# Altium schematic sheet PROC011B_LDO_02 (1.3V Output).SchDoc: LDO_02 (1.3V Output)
size 431 x 279 mm; Date: Not shown in title block; ApprovedBy: Not shown in title block; CheckedBy: Not shown in title block; Author: Not shown in title block; CompanyName: Not shown in title block; Engineer: Not shown in title block; Organization: Not shown in title block; Address1: Not shown in title block; Address2: Not shown in title block; Address3: Not shown in title block; Address4: Not shown in title block; DocumentNumber: 1; Revision: Use project parameter SCH_Rev; SheetNumber: 5; SheetTotal: 17; PageSetup: Record=PageOptions¦CenterHorizontal=True¦CenterVertical=True¦PrintScale=1.00¦XCorrection=1.00¦YCorrection=1.00¦PrintKind=0¦BorderSize=5000000¦LeftOffset=0¦BottomOffset=0¦Orientation=2¦PaperLength=1000¦PaperWidth=1000¦Scale=100¦PaperSource=15¦PrintQuality=600¦MediaType=1¦DitherType=10¦PaperKind=Letter¦PrintScaleMode=1
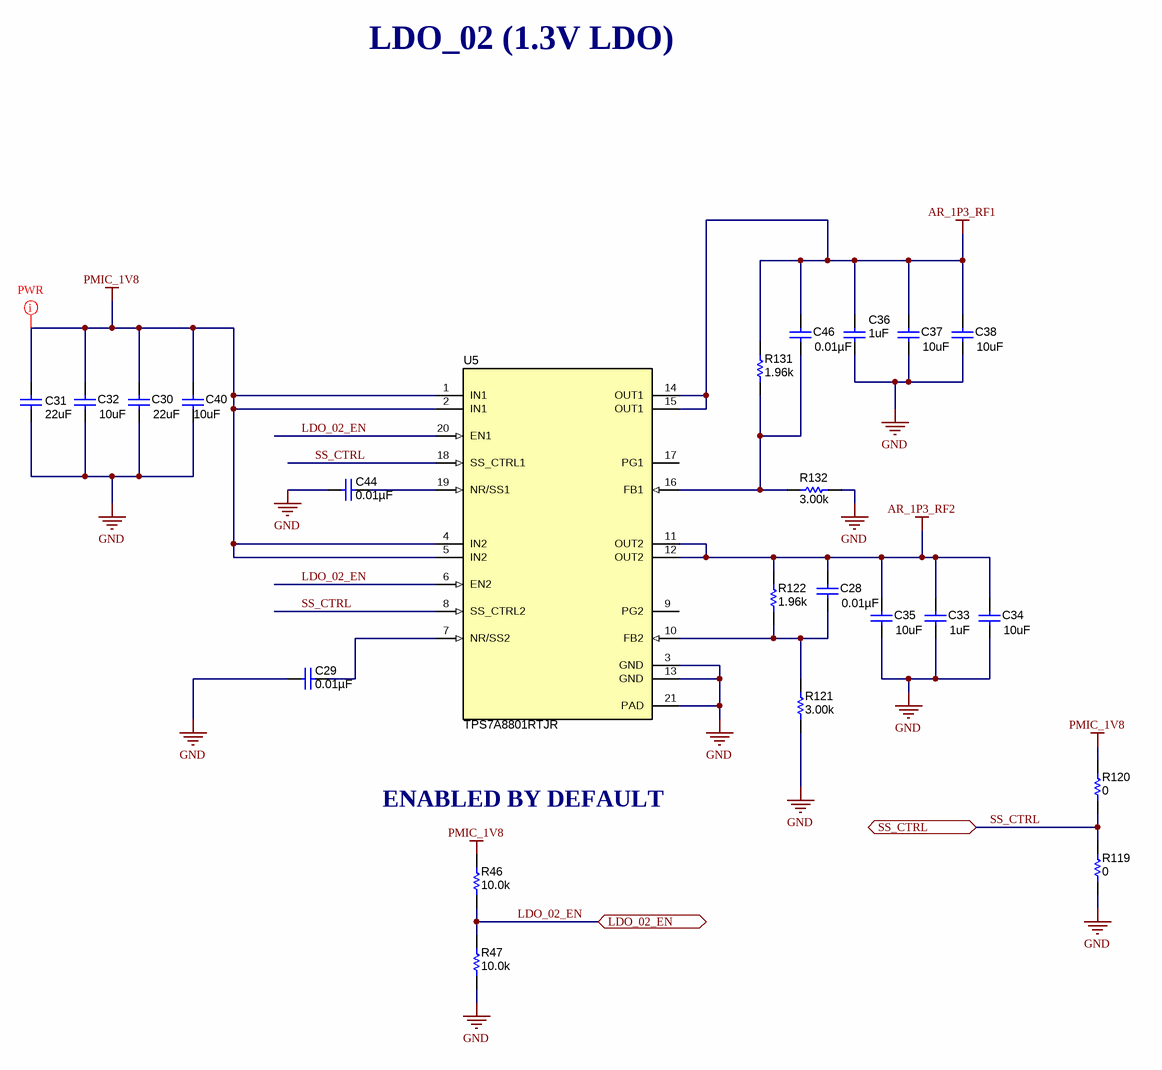
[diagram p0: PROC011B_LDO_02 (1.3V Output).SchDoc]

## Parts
C28  ValueDisplayed: 0.01µF  [0402L]  (hidden comment: CGA2B3X8R1H103K050BB)
C29  ValueDisplayed: 0.01µF  [0402L]  (hidden comment: CGA2B3X8R1H103K050BB)
C30  ValueDisplayed: 22uF  [1206_180]  (hidden comment: CGA5L1X7R0J226M160AC)
C31  ValueDisplayed: 22uF  [1206_180]  (hidden comment: CGA5L1X7R0J226M160AC)
C32  ValueDisplayed: 10uF  [0805_HV]  (hidden comment: GCM21BR71A106KE22L)
C33  ValueDisplayed: 1uF  [0603]  (hidden comment: GCM188R71C105KA64D)
C34  ValueDisplayed: 10uF  [0805_HV]  (hidden comment: GCM21BR71A106KE22L)
C35  ValueDisplayed: 10uF  [0805_HV]  (hidden comment: GCM21BR71A106KE22L)
C36  ValueDisplayed: 1uF  [0603]  (hidden comment: GCM188R71C105KA64D)
C37  ValueDisplayed: 10uF  [0805_HV]  (hidden comment: GCM21BR71A106KE22L)
C38  ValueDisplayed: 10uF  [0805_HV]  (hidden comment: GCM21BR71A106KE22L)
C40  ValueDisplayed: 10uF  [0805_HV]  (hidden comment: GCM21BR71A106KE22L)
C44  ValueDisplayed: 0.01µF  [0402L]  (hidden comment: CGA2B3X8R1H103K050BB)
C46  ValueDisplayed: 0.01µF  [0402L]  (hidden comment: CGA2B3X8R1H103K050BB)
R46  ValueDisplayed: 10.0k  [0402L]  (hidden comment: CRCW040210K0FKED)
R47  ValueDisplayed: 10.0k  [0402L]  (hidden comment: CRCW040210K0FKED)
R119  ValueDisplayed: 0  [0402L]  (hidden comment: ERJ-2GE0R00X)
R120  ValueDisplayed: 0  [0402L]  (hidden comment: ERJ-2GE0R00X)
R121  ValueDisplayed: 3.00k  [0402L]  (hidden comment: CRCW04023K00FKED)
R122  ValueDisplayed: 1.96k  [0402L]  (hidden comment: CRCW04021K96FKED)
R131  ValueDisplayed: 1.96k  [0402L]  (hidden comment: CRCW04021K96FKED)
R132  ValueDisplayed: 3.00k  [0402L]  (hidden comment: CRCW04023K00FKED)
U5  TPS7A8801RTJR  [RTJ0020D]

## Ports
LDO_02_EN, SS_CTRL

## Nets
AR_1P3_RF1: C36.2 C37.2 C38.2 C46.2 R131.2 U5.14(OUT1) U5.15(OUT1)
AR_1P3_RF2: C28.2 C33.2 C34.2 C35.2 R122.2 U5.11(OUT2) U5.12(OUT2)
GND: C29.1 C30.1 C31.1 C32.1 C33.1 C34.1 C35.1 C36.1 C37.1 C38.1 C40.1 C44.1 R47.2 R119.1 R121.1 R132.1 U5.3(GND) U5.13(GND) U5.21(PAD)
PMIC_1V8: C30.2 C31.2 C32.2 C40.2 R46.1 R120.2 U5.1(IN1) U5.2(IN1) U5.4(IN2) U5.5(IN2)
LDO_02_EN: R46.2 R47.1 U5.6(EN2) U5.20(EN1) ; port LDO_02_EN
SS_CTRL: R119.2 R120.1 U5.8(SS_CTRL2) U5.18(SS_CTRL1) ; port SS_CTRL
NetC28_1: C28.1 R121.2 R122.1 U5.10(FB2)
NetC29_2: C29.2 U5.7(NR/SS2)
NetC44_2: C44.2 U5.19(NR/SS1)
NetC46_1: C46.1 R131.1 R132.2 U5.16(FB1)

Not connected (* = marked no-connect by the designer): U5 9(PG2) 17(PG1)

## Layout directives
net class PWR: PMIC_1V8

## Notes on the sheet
- LDO_02 (1.3V LDO)
- ENABLED BY DEFAULT

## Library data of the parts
C28 C29 C44 C46 = CMP-0078224-1: CAP, CERM, 0.01 µF, 50 V,+/- 10%, X8R, AEC-Q200 Grade 0, 0402; Manufacturer: TDK; TaMin_C: -55°C; Polarized: N; SizeAreaWB_mm2: 3; U/M: EA; Value: 0.01uF; TaMax_C: 150°C; SizeZ_mm: 0.6; SizeX_mm: 1; SizeY_mm: 0.5; Cap_Case: 0402; Value2: 50V; AEC Qualified: Y; Cap_F: 10nF; AEC Grade: 0; AEC Category: Q200
C30 C31 = CMP-0008770-2: CAP, CERM, 22 uF, 6.3 V, +/- 10%, X7R, AEC-Q200 Grade 1, 1206; Manufacturer: TDK; TaMin_C: -55°C; ESR_ohm: 1.872m; Polarized: N; SizeAreaWB_mm2: 10.92; Value1: 0.001872 ohm; U/M: EA; Value: 22uF; SizeZ_mm: 1.8; SizeX_mm: 3.2; SizeY_mm: 1.6; Value2: 6.3V; SizeArea_mm2: 5.12; AEC Qualified: Y; Cap_F: 22µF; IRMS_A: 5.30203A; AEC Grade: 1; AEC Category: Q200; TaMax_C: 125°C
C32 C34 C35 C37 C38 C40 = CMP-0008017-2: CAP, CERM, 10 uF, 10 V, +/- 10%, X7R, 0805; Manufacturer: MuRata; TaMin_C: -55°C; Polarized: N; SizeAreaWB_mm2: 6.75; Value1: Unknown; U/M: EA; Value: 10uF; TaMax_C: 125°C; SizeZ_mm: 1.45; SizeX_mm: 2; SizeY_mm: 1.25; Cap_Case: 0805; Value2: 10V; SizeArea_mm2: 2.5; CompType: Capacitor; Cap_F: 10µF; AEC Category: Q200
C33 C36 = CMP-0007136-5: CAP, CERM, 1 uF, 16 V, +/- 10%, X7R, AEC-Q200 Grade 1, 0603; Manufacturer: MuRata; TaMin_C: -55°C; Polarized: N; SizeAreaWB_mm2: 4.68; Value1: Unknown; U/M: EA; Value: 1uF; TaMax_C: 125°C; SizeZ_mm: 1; SizeX_mm: 1.6; SizeY_mm: 0.8; Value2: 16V; SizeArea_mm2: 1.28; AEC Qualified: Y; Cap_F: 1µF; AEC Category: Q200
R46 = CMP-0025958-2: RES, 10.0 k, 1%, 0.063 W, 0402; Manufacturer: Vishay-Dale; Power_W: 63mW; TempCo: 100 ppm/C; Value_Code: 10k0; U/M: EA; Value: 10.0k; EIA_Code: E96; Res_ohm: 10k; SizeX_mm: 1; SizeY_mm: 0.5; SizeZ_mm: 0.6; Value2: 0.063W; VDC_V: 50V; AEC Category: Q200
R47 = CMP-0025958-2: RES, 10.0 k, 1%, 0.063 W, 0402; Manufacturer: Vishay-Dale; Power_W: 63mW; TempCo: 100 ppm/C; Value_Code: 10k0; U/M: EA; Value: 10.0k; EIA_Code: E96; Res_ohm: 10k; SizeX_mm: 1; SizeY_mm: 0.5; SizeZ_mm: 0.6; Value2: 0.063W; CompType: Resistor; VDC_V: 50V; AEC Category: Q200; INSTALATION: DNP
R119 = CMP-0026992-2: RES, 0, 5%, 0.063 W, 0402; Manufacturer: Panasonic; Power_W: 63mW; TempCo: 600 ppm/C; Value_Code: 0000; U/M: EA; Value: 0; EIA_Code: E24; SizeX_mm: 1; SizeY_mm: 0.5; SizeZ_mm: 0.6; Value2: 0.063W; VDC_V: 50V; AEC Category: Q200
R120 = CMP-0026992-2: RES, 0, 5%, 0.063 W, 0402; Manufacturer: Panasonic; Power_W: 63mW; TempCo: 600 ppm/C; Value_Code: 0000; U/M: EA; Value: 0; EIA_Code: E24; SizeX_mm: 1; SizeY_mm: 0.5; SizeZ_mm: 0.6; Value2: 0.063W; CompType: Resistor; VDC_V: 50V; AEC Category: Q200; INSTALATION: DNP
R121 = CMP-0078211-1: RES, 3.00 k, 1%, 0.063 W, AEC-Q200 Grade 0, 0402; Manufacturer: Vishay-Dale; Value_Code: 3k00; SizeArea_mm2: 0.5; AEC Qualified: Y; AEC Category: Q200; Res_ohm: 3k; Value: 3.00k; SizeZ_mm: 0.6; TempCo: 100 ppm/C; AEC Grade: 0; Power_W: 63mW; VDC_V: 50V; Value2: 0.063W; U/M: EA; CompType: Resistor; SizeX_mm: 1
R122 R131 = CMP-0026099-1: RES, 1.96 k, 1%, 0.063 W, 0402; Manufacturer: Vishay-Dale; Power_W: 63mW; TempCo: 100 ppm/C; Value_Code: 1k96; U/M: EA; Value: 1.96k; EIA_Code: E96; SizeX_mm: 1; SizeY_mm: 0.5; SizeZ_mm: 0.6; Value2: 0.063W; CompType: Resistor; VDC_V: 50V; AEC Category: Q200
R132 = CMP-0078211-1: RES, 3.00 k, 1%, 0.063 W, AEC-Q200 Grade 0, 0402; Manufacturer: Vishay-Dale; Value_Code: 3k00; SizeArea_mm2: 0.5; AEC Qualified: Y; AEC Category: Q200; Res_ohm: 3k; Value: 3.00k; SizeZ_mm: 0.6; TempCo: 100 ppm/C; AEC Grade: 0; Power_W: 63mW; VDC_V: 50V; Value2: 0.063W; U/M: EA; SizeX_mm: 1
U5 = CMP-0073732-2: Dual, 1-A, Low Noise (3.8-uVRMS), LDO Voltage Regulator, RTJ0020D (WQFN-20); Alternate PartNumber: TPS7A8801RTJT; Alternate Manufacturer: Texas Instruments; Green_Lifecycle: Active; SizeAreaWB_mm2: 25.0; Green_REACh: Passed; U/M: EA; SizeZ_mm: 0.8; SizeX_mm: 4.0; SizeArea_mm2: 16.0; CompType: IC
